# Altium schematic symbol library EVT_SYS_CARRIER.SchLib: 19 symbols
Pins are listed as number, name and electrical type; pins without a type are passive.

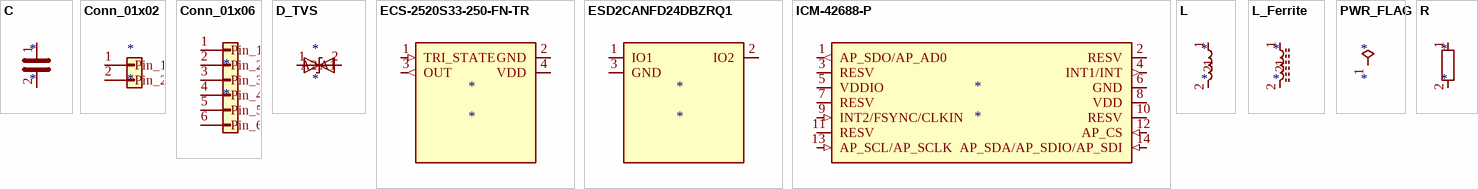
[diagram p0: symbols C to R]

## C
designator *
pins: 1, 2

## Conn_01x02
designator *
pins: 1 Pin_1, 2 Pin_2

## Conn_01x06
designator *
pins: 1 Pin_1, 2 Pin_2, 3 Pin_3, 4 Pin_4, 5 Pin_5, 6 Pin_6

## D_TVS
designator *
pins: 1 A1, 2 A2

## ECS-2520S33-250-FN-TR
designator *
pins: 1 TRI_STATE (in), 2 GND (power), 3 OUT (out), 4 VDD (power)

## ESD2CANFD24DBZRQ1
designator *
pins: 1 IO1 (io), 2 IO2 (io), 3 GND

## ICM-42688-P
designator *
pins: 1 AP_SDO/AP_AD0 (out), 2 RESV, 3 RESV, 4 INT1/INT (out), 5 VDDIO (power), 6 GND (power), 7 RESV, 8 VDD (power), 9 INT2/FSYNC/CLKIN (in), 10 RESV, 11 RESV, 12 AP_CS (in), 13 AP_SCL/AP_SCLK (in), 14 AP_SDA/AP_SDIO/AP_SDI (in)

## L
designator *
pins: 1, 2

## L_Ferrite
designator *
pins: 1, 2

## PWR_FLAG
designator *  (graphical)
pins: 1 (power)

## R
designator *
pins: 1, 2

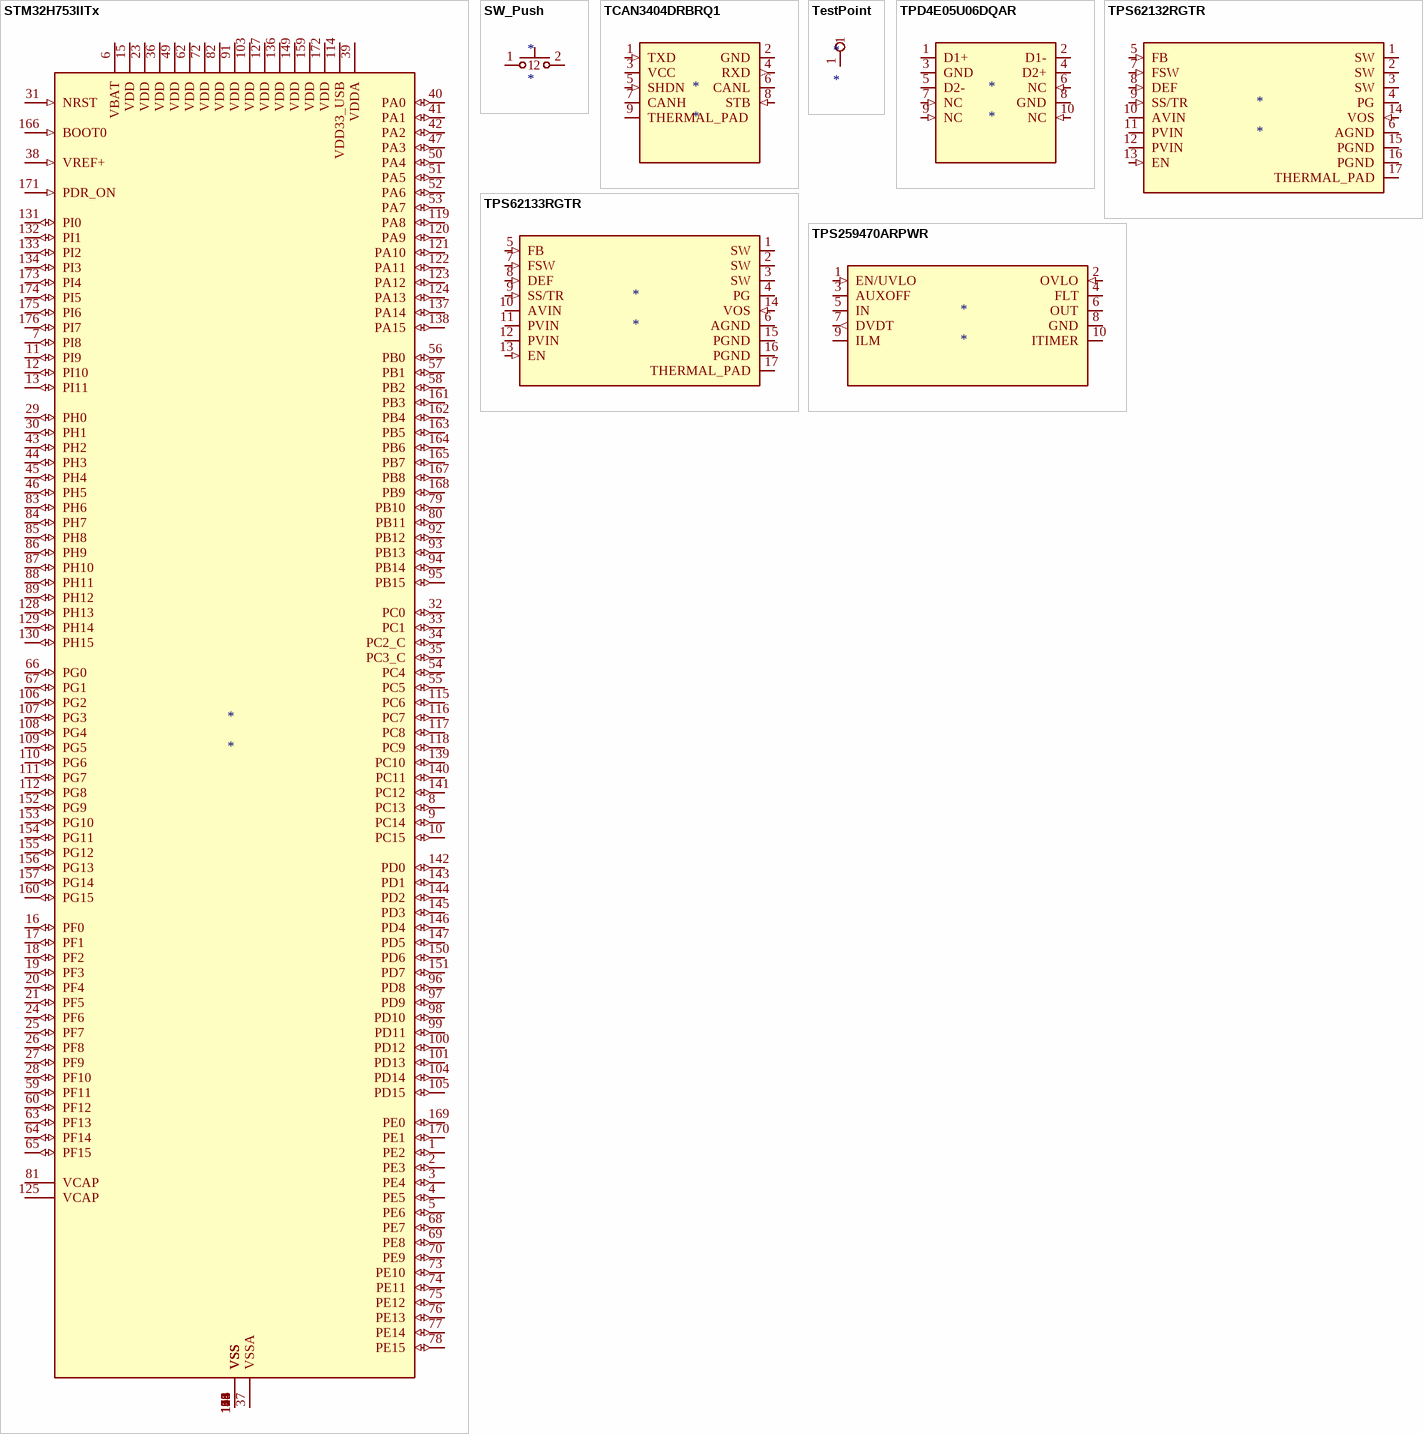
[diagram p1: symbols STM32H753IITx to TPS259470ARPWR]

## STM32H753IITx
designator *
pins: 1 PE2 (io), 2 PE3 (io), 3 PE4 (io), 4 PE5 (io), 5 PE6 (io), 6 VBAT (power), 7 PI8 (io), 8 PC13 (io), 9 PC14 (io), 10 PC15 (io), 11 PI9 (io), 12 PI10 (io), 13 PI11 (io), 14 VSS (power), 15 VDD (power), 16 PF0 (io), 17 PF1 (io), 18 PF2 (io), 19 PF3 (io), 20 PF4 (io), 21 PF5 (io), 22 VSS, 23 VDD (power), 24 PF6 (io), 25 PF7 (io), 26 PF8 (io), 27 PF9 (io), 28 PF10 (io), 29 PH0 (io), 30 PH1 (io), 31 NRST (in), 32 PC0 (io), 33 PC1 (io), 34 PC2_C (io), 35 PC3_C (io), 36 VDD (power), 37 VSSA (power), 38 VREF+ (in), 39 VDDA (power), 40 PA0 (io), 41 PA1 (io), 42 PA2 (io), 43 PH2 (io), 44 PH3 (io), 45 PH4 (io), 46 PH5 (io), 47 PA3 (io), 48 VSS, 49 VDD (power), 50 PA4 (io), 51 PA5 (io), 52 PA6 (io), 53 PA7 (io), 54 PC4 (io), 55 PC5 (io), 56 PB0 (io), 57 PB1 (io), 58 PB2 (io), 59 PF11 (io), 60 PF12 (io), 61 VSS, 62 VDD (power), 63 PF13 (io), 64 PF14 (io), 65 PF15 (io), 66 PG0 (io), 67 PG1 (io), 68 PE7 (io), 69 PE8 (io), 70 PE9 (io), 71 VSS, 72 VDD (power), 73 PE10 (io), 74 PE11 (io), 75 PE12 (io), 76 PE13 (io), 77 PE14 (io), 78 PE15 (io), 79 PB10 (io), 80 PB11 (io), 81 VCAP (power), 82 VDD (power), 83 PH6 (io), 84 PH7 (io), 85 PH8 (io), 86 PH9 (io), 87 PH10 (io), 88 PH11 (io), 89 PH12 (io), 90 VSS, 91 VDD (power), 92 PB12 (io), 93 PB13 (io), 94 PB14 (io), 95 PB15 (io), 96 PD8 (io), 97 PD9 (io), 98 PD10 (io), 99 PD11 (io), 100 PD12 (io), 101 PD13 (io), 102 VSS, 103 VDD (power), 104 PD14 (io), 105 PD15 (io), 106 PG2 (io), 107 PG3 (io), 108 PG4 (io), 109 PG5 (io), 110 PG6 (io), 111 PG7 (io), 112 PG8 (io), 113 VSS, 114 VDD33_USB (power), 115 PC6 (io), 116 PC7 (io), 117 PC8 (io), 118 PC9 (io), 119 PA8 (io), 120 PA9 (io), 121 PA10 (io), 122 PA11 (io), 123 PA12 (io), 124 PA13 (io), 125 VCAP (power), 126 VSS, 127 VDD (power), 128 PH13 (io), 129 PH14 (io), 130 PH15 (io), 131 PI0 (io), 132 PI1 (io), 133 PI2 (io), 134 PI3 (io), 135 VSS, 136 VDD (power), 137 PA14 (io), 138 PA15 (io), 139 PC10 (io), 140 PC11 (io), 141 PC12 (io), 142 PD0 (io), 143 PD1 (io), 144 PD2 (io), 145 PD3 (io), 146 PD4 (io), 147 PD5 (io), 148 VSS, 149 VDD (power), 150 PD6 (io), 151 PD7 (io), 152 PG9 (io), 153 PG10 (io), 154 PG11 (io), 155 PG12 (io), 156 PG13 (io), 157 PG14 (io), 158 VSS, 159 VDD (power), 160 PG15 (io), 161 PB3 (io), 162 PB4 (io), 163 PB5 (io), 164 PB6 (io), 165 PB7 (io), 166 BOOT0 (in), 167 PB8 (io), 168 PB9 (io), 169 PE0 (io), 170 PE1 (io), 171 PDR_ON (in), 172 VDD (power), 173 PI4 (io), 174 PI5 (io), 175 PI6 (io), 176 PI7 (io)

## SW_Push
designator *
pins: 1, 2

## TCAN3404DRBRQ1
designator *
pins: 1 TXD (in), 2 GND (power), 3 VCC (power), 4 RXD (out), 5 SHDN (in), 6 CANL (io), 7 CANH (io), 8 STB (in), 9 THERMAL_PAD (power)

## TestPoint
designator *
pins: 1

## TPD4E05U06DQAR
designator *
pins: 1 D1+ (io), 2 D1- (io), 3 GND, 4 D2+ (io), 5 D2- (io), 6 NC (in), 7 NC (in), 8 GND, 9 NC (in), 10 NC (in)

## TPS62132RGTR
designator *
pins: 1 SW, 2 SW, 3 SW, 4 PG (oc), 5 FB (in), 6 AGND (power), 7 FSW (in), 8 DEF (in), 9 SS/TR (in), 10 AVIN (power), 11 PVIN (power), 12 PVIN (power), 13 EN (in), 14 VOS (in), 15 PGND (power), 16 PGND (power), 17 THERMAL_PAD (power)

## TPS62133RGTR
designator *
pins: 1 SW, 2 SW, 3 SW, 4 PG (oc), 5 FB (in), 6 AGND (power), 7 FSW (in), 8 DEF (in), 9 SS/TR (in), 10 AVIN (power), 11 PVIN (power), 12 PVIN (power), 13 EN (in), 14 VOS (in), 15 PGND (power), 16 PGND (power), 17 THERMAL_PAD (power)

## TPS259470ARPWR
designator *
pins: 1 EN/UVLO (in), 2 OVLO (in), 3 AUXOFF (oc), 4 FLT (oc), 5 IN (power), 6 OUT (power), 7 DVDT (out), 8 GND (power), 9 ILM (io), 10 ITIMER (io)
